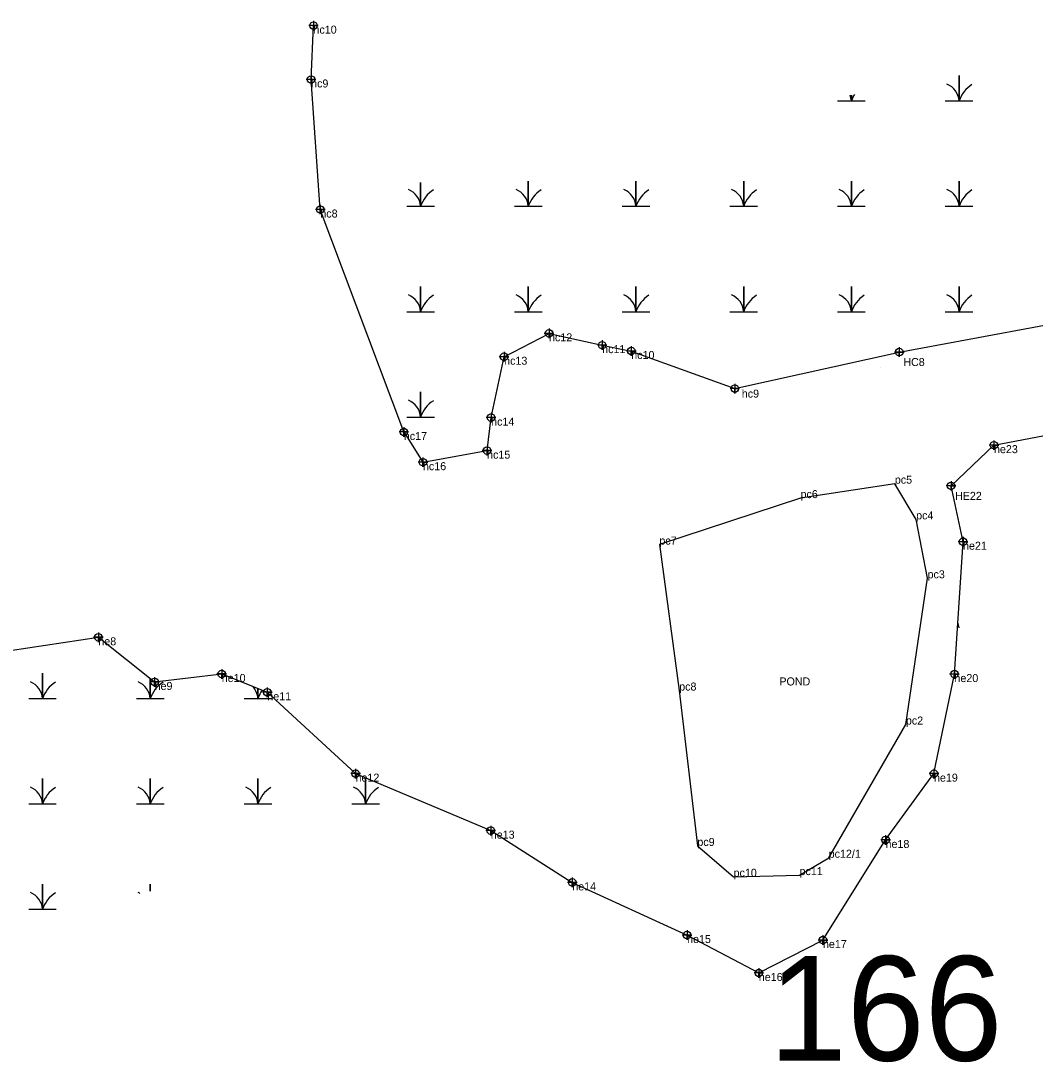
# Model space of a CAD drawing. Extents: x 2072529 to 2268796, y 436423 to 470406.
# Drawn here: x 2184796 to 2185430, y 452796 to 453446 of the extents above; entities that cross this region are included whole.
import ezdxf

# ---------------------------------------------------------------- set-up
doc = ezdxf.new("R2010")
doc.units = 0
for name, color, linetype in [('Default', 7, 'Continuous'), ('Exist Environmental Wetland Boundary', 7, 'Continuous'), ('Exist Environmental Wetland Boundary Cogo Comment', 7, 'Continuous'), ('Exist Environmental Wetland Boundary Cogo Point CELL', 7, 'Continuous'), ('Exist Hydro Jurisdictional Stream or Body of Water NEU Mitigable Cogo Comment', 7, 'Continuous'), ('Old_Level_20', 7, 'Continuous'), ('Old_Level_52', 7, 'Continuous')]:
    doc.layers.add(name, color=color, linetype=linetype)

msp = doc.modelspace()

# ---------------------------------------------------------------- linework, layer by layer
at = {"layer": 'Exist Environmental Wetland Boundary'}
for points in [[(2184979.12, 453446.03), (2184979.12, 453440.03), (2184979.12, 453443.03), (2184982.12, 453443.03), (2184976.12, 453443.03)], [(2184977.65, 453412.42), (2184977.65, 453406.42), (2184977.65, 453409.42), (2184980.65, 453409.42), (2184974.65, 453409.42)], [(2184983.4, 453331.2), (2184983.4, 453325.2), (2184983.4, 453328.2), (2184986.4, 453328.2), (2184980.4, 453328.2)], [(2185126.21, 453253.87), (2185126.21, 453247.87), (2185126.21, 453250.87), (2185129.21, 453250.87), (2185123.21, 453250.87)], [(2185159.4, 453246.51), (2185159.4, 453240.51), (2185159.4, 453243.51), (2185162.4, 453243.51), (2185156.4, 453243.51)], [(2185098.16, 453239.27), (2185098.16, 453233.27), (2185098.16, 453236.27), (2185101.16, 453236.27), (2185095.16, 453236.27)], [(2185177.54, 453242.84), (2185177.54, 453236.84), (2185177.54, 453239.84), (2185180.54, 453239.84), (2185174.54, 453239.84)], [(2185344.94, 453242.21), (2185344.94, 453236.21), (2185344.94, 453239.21), (2185347.94, 453239.21), (2185341.94, 453239.21)], [(2185242.22, 453219.35), (2185242.22, 453213.35), (2185242.22, 453216.35), (2185245.22, 453216.35), (2185239.22, 453216.35)], [(2185090.05, 453201.25), (2185090.05, 453195.25), (2185090.05, 453198.25), (2185093.05, 453198.25), (2185087.05, 453198.25)], [(2185035.54, 453192.27), (2185035.54, 453186.27), (2185035.54, 453189.27), (2185038.54, 453189.27), (2185032.54, 453189.27)], [(2185087.53, 453180.63), (2185087.53, 453174.63), (2185087.53, 453177.63), (2185090.53, 453177.63), (2185084.53, 453177.63)], [(2185404.06, 453184.06), (2185404.06, 453178.06), (2185404.06, 453181.06), (2185407.06, 453181.06), (2185401.06, 453181.06)], [(2185047.47, 453173.42), (2185047.47, 453167.42), (2185047.47, 453170.42), (2185050.47, 453170.42), (2185044.47, 453170.42)], [(2185377.23, 453158.63), (2185377.23, 453152.63), (2185377.23, 453155.63), (2185380.23, 453155.63), (2185374.23, 453155.63)], [(2185384.73, 453123.74), (2185384.73, 453117.74), (2185384.73, 453120.74), (2185387.73, 453120.74), (2185381.73, 453120.74)], [(2184844.78, 453064.05), (2184844.78, 453058.05), (2184844.78, 453061.05), (2184847.78, 453061.05), (2184841.78, 453061.05)], [(2184879.9, 453036.18), (2184879.9, 453030.18), (2184879.9, 453033.18), (2184882.9, 453033.18), (2184876.9, 453033.18)], [(2184921.85, 453041.15), (2184921.85, 453035.15), (2184921.85, 453038.15), (2184924.85, 453038.15), (2184918.85, 453038.15)], [(2185379.38, 453041.1), (2185379.38, 453035.1), (2185379.38, 453038.1), (2185382.38, 453038.1), (2185376.38, 453038.1)], [(2184950.29, 453029.71), (2184950.29, 453023.71), (2184950.29, 453026.71), (2184953.29, 453026.71), (2184947.29, 453026.71)], [(2185005.39, 452978.93), (2185005.39, 452972.93), (2185005.39, 452975.93), (2185008.39, 452975.93), (2185002.39, 452975.93)], [(2185366.6, 452978.91), (2185366.6, 452972.91), (2185366.6, 452975.91), (2185369.6, 452975.91), (2185363.6, 452975.91)], [(2185089.84, 452943.32), (2185089.84, 452937.32), (2185089.84, 452940.32), (2185092.84, 452940.32), (2185086.84, 452940.32)], [(2185336.35, 452937.49), (2185336.35, 452931.49), (2185336.35, 452934.49), (2185339.35, 452934.49), (2185333.35, 452934.49)], [(2185140.72, 452911), (2185140.72, 452905), (2185140.72, 452908), (2185143.72, 452908), (2185137.72, 452908)], [(2185212.43, 452878.12), (2185212.43, 452872.12), (2185212.43, 452875.12), (2185215.43, 452875.12), (2185209.43, 452875.12)], [(2185297.24, 452875.01), (2185297.24, 452869.01), (2185297.24, 452872.01), (2185300.24, 452872.01), (2185294.24, 452872.01)], [(2185257.21, 452854.43), (2185257.21, 452848.43), (2185257.21, 452851.43), (2185260.21, 452851.43), (2185254.21, 452851.43)]]:
    msp.add_lwpolyline(points, dxfattribs=at)
for centre in [(2184979.12, 453443.03), (2184977.65, 453409.42), (2184983.4, 453328.2), (2185126.21, 453250.87), (2185159.4, 453243.51), (2185098.16, 453236.27), (2185177.54, 453239.84), (2185344.94, 453239.21), (2185242.22, 453216.35), (2185090.05, 453198.25), (2185035.54, 453189.27), (2185087.53, 453177.63), (2185404.06, 453181.06), (2185047.47, 453170.42), (2185377.23, 453155.63), (2185384.73, 453120.74), (2184844.78, 453061.05), (2184921.85, 453038.15), (2185379.38, 453038.1), (2184879.9, 453033.18), (2184950.29, 453026.71), (2185005.39, 452975.93), (2185366.6, 452975.91), (2185089.84, 452940.32), (2185336.35, 452934.49), (2185140.72, 452908), (2185212.43, 452875.12), (2185297.24, 452872.01), (2185257.21, 452851.43)]:
    msp.add_circle(centre, 2.34, dxfattribs=at)
at = {"layer": 'Exist Environmental Wetland Boundary Cogo Point CELL'}
for points in [[(2185373.67, 453396.01), (2185382.27, 453396.01), (2185382.27, 453411.79), (2185382.27, 453396.01), (2185390.87, 453396.01)], [(2185306.42, 453396.01), (2185315.02, 453396.01), (2185315.02, 453399.69)], [(2185315.02, 453399.69), (2185315.02, 453396.01), (2185323.62, 453396.01)], [(2185037.42, 453330.21), (2185046.02, 453330.21), (2185046.02, 453345)], [(2185046.02, 453345), (2185046.02, 453330.21), (2185054.62, 453330.21)], [(2185104.67, 453330.21), (2185113.27, 453330.21), (2185113.27, 453345.99), (2185113.27, 453330.21), (2185121.87, 453330.21)], [(2185171.92, 453330.21), (2185180.52, 453330.21), (2185180.52, 453345.99), (2185180.52, 453330.21), (2185189.12, 453330.21)], [(2185239.17, 453330.21), (2185247.77, 453330.21), (2185247.77, 453345.99), (2185247.77, 453330.21), (2185256.37, 453330.21)], [(2185306.42, 453330.21), (2185315.02, 453330.21), (2185315.02, 453345.99), (2185315.02, 453330.21), (2185323.62, 453330.21)], [(2185373.67, 453330.21), (2185382.27, 453330.21), (2185382.27, 453345.99), (2185382.27, 453330.21), (2185390.87, 453330.21)], [(2185037.42, 453264.41), (2185046.02, 453264.41), (2185046.02, 453280.19), (2185046.02, 453264.41), (2185054.62, 453264.41)], [(2185104.67, 453264.41), (2185113.27, 453264.41), (2185113.27, 453280.19), (2185113.27, 453264.41), (2185121.87, 453264.41)], [(2185171.92, 453264.41), (2185180.52, 453264.41), (2185180.52, 453280.19), (2185180.52, 453264.41), (2185189.12, 453264.41)], [(2185239.17, 453264.41), (2185247.77, 453264.41), (2185247.77, 453280.19), (2185247.77, 453264.41), (2185256.37, 453264.41)], [(2185306.42, 453264.41), (2185315.02, 453264.41), (2185315.02, 453280.19), (2185315.02, 453264.41), (2185323.62, 453264.41)], [(2185373.67, 453264.41), (2185382.27, 453264.41), (2185382.27, 453280.19), (2185382.27, 453264.41), (2185390.87, 453264.41)], [(2185037.42, 453198.61), (2185046.02, 453198.61), (2185046.02, 453214.39), (2185046.02, 453198.61), (2185054.62, 453198.61)], [(2184801.35, 453022.81), (2184809.95, 453022.81), (2184809.95, 453038.59), (2184809.95, 453022.81), (2184818.55, 453022.81)], [(2184868.6, 453022.81), (2184877.2, 453022.81), (2184877.2, 453035.32)], [(2184877.2, 453035.32), (2184877.2, 453022.81), (2184885.8, 453022.81)], [(2184935.85, 453022.81), (2184944.45, 453022.81), (2184944.45, 453029.06)], [(2184944.45, 453029.06), (2184944.45, 453022.81), (2184953.05, 453022.81)], [(2184801.35, 452957.01), (2184809.95, 452957.01), (2184809.95, 452972.79), (2184809.95, 452957.01), (2184818.55, 452957.01)], [(2184868.6, 452957.01), (2184877.2, 452957.01), (2184877.2, 452972.79), (2184877.2, 452957.01), (2184885.8, 452957.01)], [(2184935.85, 452957.01), (2184944.45, 452957.01), (2184944.45, 452972.79), (2184944.45, 452957.01), (2184953.05, 452957.01)], [(2185003.1, 452957.01), (2185011.7, 452957.01), (2185011.7, 452972.79), (2185011.7, 452957.01), (2185020.3, 452957.01)], [(2184801.35, 452891.21), (2184809.95, 452891.21), (2184809.95, 452906.99), (2184809.95, 452891.21), (2184818.55, 452891.21)], [(2184877.2, 452902.49), (2184877.2, 452906.99), (2184877.2, 452902.49)]]:
    msp.add_lwpolyline(points, dxfattribs=at)
for centre, radius, start, end in [((2185370, 453395.12), 12.3, 4.14034, 67.53497), ((2185400.51, 453389.95), 19.22, 122.12745, 161.62219), ((2185333.26, 453389.95), 19.22, 148.17741, 161.62219), ((2185302.75, 453395.12), 12.3, 4.14034, 21.0382), ((2185033.75, 453329.32), 12.3, 4.14034, 67.53497), ((2185064.26, 453324.15), 19.22, 122.12745, 161.62219), ((2185101, 453329.32), 12.3, 4.14034, 67.53497), ((2185131.51, 453324.15), 19.22, 122.12745, 161.62219), ((2185168.25, 453329.32), 12.3, 4.14034, 67.53497), ((2185198.76, 453324.15), 19.22, 122.12745, 161.62219), ((2185235.5, 453329.32), 12.3, 4.14034, 67.53497), ((2185266.01, 453324.15), 19.22, 122.12745, 161.62219), ((2185302.75, 453329.32), 12.3, 4.14034, 67.53497), ((2185333.26, 453324.15), 19.22, 122.12745, 161.62219), ((2185370, 453329.32), 12.3, 4.14034, 67.53497), ((2185400.51, 453324.15), 19.22, 122.12745, 161.62219), ((2185033.75, 453263.52), 12.3, 4.14034, 67.53497), ((2185064.26, 453258.35), 19.22, 122.12745, 161.62219), ((2185101, 453263.52), 12.3, 4.14034, 67.53497), ((2185131.51, 453258.35), 19.22, 122.12745, 161.62219), ((2185168.25, 453263.52), 12.3, 4.14034, 67.53497), ((2185198.76, 453258.35), 19.22, 122.12745, 161.62219), ((2185235.5, 453263.52), 12.3, 4.14034, 67.53497), ((2185266.01, 453258.35), 19.22, 122.12745, 161.62219), ((2185302.75, 453263.52), 12.3, 4.14034, 67.53497), ((2185333.26, 453258.35), 19.22, 122.12745, 161.62219), ((2185370, 453263.52), 12.3, 4.14034, 67.53497), ((2185400.51, 453258.35), 19.22, 122.12745, 161.62219), ((2185033.75, 453197.72), 12.3, 4.14034, 67.53497), ((2185064.26, 453192.55), 19.22, 122.12745, 161.62219), ((2185370, 453066.12), 12.3, 4.14034, 21.05335), ((2184797.68, 453021.92), 12.3, 4.14034, 67.53497), ((2184828.19, 453016.75), 19.22, 122.12745, 161.62219), ((2184864.93, 453021.92), 12.3, 4.14034, 67.53497), ((2184895.44, 453016.75), 19.22, 122.12745, 161.62219), ((2184932.18, 453021.92), 12.3, 4.14034, 43.67086), ((2184962.69, 453016.75), 19.22, 144.20108, 161.62219), ((2184797.68, 452956.12), 12.3, 4.14034, 67.53497), ((2184828.19, 452950.95), 19.22, 122.12745, 161.62219), ((2184864.93, 452956.12), 12.3, 4.14034, 67.53497), ((2184895.44, 452950.95), 19.22, 122.12745, 161.62219), ((2184932.18, 452956.12), 12.3, 4.14034, 67.53497), ((2184962.69, 452950.95), 19.22, 122.12745, 161.62219), ((2184999.43, 452956.12), 12.3, 4.14034, 67.53497), ((2185029.94, 452950.95), 19.22, 122.12745, 161.62219), ((2184797.68, 452890.32), 12.3, 4.14034, 67.53497), ((2184828.19, 452885.15), 19.22, 122.12745, 161.62219), ((2184864.93, 452890.32), 12.3, 61.92098, 67.53497)]:
    msp.add_arc(centre, radius, start, end, dxfattribs=at)
at = {"layer": 'Old_Level_20'}
for p, q in [((2184979.12, 453443.03), (2184979.12, 453443.03)), ((2184977.65, 453409.42), (2184977.65, 453409.42)), ((2184983.4, 453328.2), (2184983.4, 453328.2)), ((2185126.21, 453250.87), (2185126.21, 453250.87)), ((2185159.4, 453243.51), (2185159.4, 453243.51)), ((2185177.54, 453239.84), (2185177.54, 453239.84)), ((2185098.16, 453236.27), (2185098.16, 453236.27)), ((2185332.93, 453229.41), (2185332.93, 453229.41)), ((2185246.58, 453215.74), (2185246.58, 453215.74)), ((2185090.05, 453198.25), (2185090.05, 453198.25)), ((2185035.54, 453189.27), (2185035.54, 453189.27)), ((2185404.06, 453181.06), (2185404.06, 453181.06)), ((2185087.53, 453177.63), (2185087.53, 453177.63)), ((2185047.47, 453170.42), (2185047.47, 453170.42)), ((2185379.42, 453161.76), (2185379.42, 453161.76)), ((2185342.14, 453156.99), (2185342.14, 453156.99)), ((2185283.27, 453147.97), (2185283.27, 453147.97)), ((2185355.44, 453134.7), (2185355.44, 453134.7)), ((2185384.73, 453120.74), (2185384.73, 453120.74)), ((2185195.12, 453118.93), (2185195.12, 453118.93)), ((2185362.58, 453097.89), (2185362.58, 453097.89)), ((2184844.78, 453061.05), (2184844.78, 453061.05)), ((2184921.85, 453038.15), (2184921.85, 453038.15)), ((2185379.38, 453038.1), (2185379.38, 453038.1)), ((2184879.9, 453033.18), (2184879.9, 453033.18)), ((2184950.29, 453026.71), (2184950.29, 453026.71)), ((2185207.48, 453027.8), (2185207.48, 453027.8)), ((2185349.06, 453006.57), (2185349.06, 453006.57)), ((2185005.39, 452975.93), (2185005.39, 452975.93)), ((2185366.6, 452975.91), (2185366.6, 452975.91)), ((2185089.84, 452940.32), (2185089.84, 452940.32)), ((2185336.35, 452934.49), (2185336.35, 452934.49)), ((2185218.84, 452930.77), (2185218.84, 452930.77)), ((2185300.84, 452923.4), (2185300.84, 452923.4)), ((2185282.63, 452912.55), (2185282.63, 452912.55)), ((2185140.72, 452908), (2185140.72, 452908)), ((2185241.45, 452911.51), (2185241.45, 452911.51)), ((2185212.43, 452875.12), (2185212.43, 452875.12)), ((2185297.24, 452872.01), (2185297.24, 452872.01)), ((2185257.21, 452851.43), (2185257.21, 452851.43))]:
    msp.add_line(p, q, dxfattribs=at)
for points in [[(2185035.54, 453189.27), (2184983.4, 453328.2), (2184977.65, 453409.42), (2184979.12, 453443.03)], [(2185035.54, 453189.27), (2184983.4, 453328.2), (2184977.65, 453409.42), (2184979.12, 453443.03)], [(2185035.54, 453189.27), (2185047.47, 453170.42), (2185087.53, 453177.63), (2185090.05, 453198.25), (2185098.16, 453236.27), (2185126.21, 453250.87), (2185159.4, 453243.51), (2185177.54, 453239.84), (2185242.22, 453216.35), (2185344.94, 453239.21), (2185481.7, 453264.48), (2185602.96, 453294.86), (2185721.74, 453322.09), (2185796.34, 453338.15), (2185846.75, 453343.9), (2185952.49, 453364.25), (2185987.26, 453373.96), (2186006.22, 453363.32), (2186024.19, 453324.8)], [(2185035.54, 453189.27), (2185047.47, 453170.42), (2185087.53, 453177.63), (2185090.05, 453198.25), (2185098.16, 453236.27), (2185126.21, 453250.87), (2185159.4, 453243.51), (2185177.54, 453239.84)], [(2184734.36, 453044.59), (2184844.78, 453061.05), (2184879.9, 453033.18), (2184921.85, 453038.15), (2184950.29, 453026.71), (2185005.39, 452975.93), (2185089.84, 452940.32), (2185140.72, 452908), (2185212.43, 452875.12), (2185257.21, 452851.43), (2185297.24, 452872.01), (2185336.35, 452934.49), (2185366.6, 452975.91), (2185379.38, 453038.1), (2185384.73, 453120.74), (2185377.23, 453155.63), (2185404.06, 453181.06), (2185488.04, 453196.98)], [(2184430.06, 452870.49), (2184414.61, 452891.04), (2184410.74, 452919.14), (2184389.78, 452979.2), (2184468.45, 452994.37), (2184572.88, 453014.51), (2184734.36, 453044.59), (2184844.78, 453061.05), (2184879.9, 453033.18), (2184921.85, 453038.15), (2184950.29, 453026.71), (2185005.39, 452975.93), (2185089.84, 452940.32), (2185140.72, 452908), (2185212.43, 452875.12), (2185257.21, 452851.43), (2185297.24, 452872.01), (2185336.35, 452934.49), (2185366.6, 452975.91), (2185379.38, 453038.1), (2185384.73, 453120.74)]]:
    msp.add_lwpolyline(points, dxfattribs=at)
at = {"layer": 'Old_Level_52'}
msp.add_lwpolyline([(2185300.84, 452923.4), (2185349.06, 453006.57), (2185362.58, 453097.89), (2185355.44, 453134.7), (2185342.14, 453156.99), (2185283.27, 453147.97), (2185195.12, 453118.93), (2185207.48, 453027.8), (2185218.84, 452930.77), (2185241.45, 452911.51), (2185282.63, 452912.55)], close=True, dxfattribs=at)

# ---------------------------------------------------------------- texts
at = {"layer": 'Default'}
msp.add_text('166', height=65.34, dxfattribs=at).set_placement((2185263.56, 452796.66))
at = {"layer": 'Exist Environmental Wetland Boundary Cogo Comment'}
for s, p in [('hc10', (2184979.12, 453438.03)), ('hc9', (2184977.65, 453404.42)), ('hc8', (2184983.4, 453323.2)), ('hc12', (2185126.21, 453245.87)), ('hc11', (2185159.4, 453238.51)), ('hc10', (2185177.54, 453234.84)), ('hc13', (2185098.16, 453231.27)), ('HC8', (2185347.44, 453230.46)), ('hc9', (2185246.58, 453210.74)), ('hc14', (2185090.05, 453193.25)), ('hc17', (2185035.54, 453184.27)), ('he23', (2185404.06, 453176.06)), ('hc15', (2185087.53, 453172.63)), ('hc16', (2185047.47, 453165.42)), ('HE22', (2185379.73, 453146.88)), ('he21', (2185384.73, 453115.74)), ('he8', (2184844.78, 453056.05)), ('he10', (2184921.85, 453033.15)), ('he20', (2185379.38, 453033.1)), ('he9', (2184879.9, 453028.18)), ('he11', (2184950.29, 453021.71)), ('he12', (2185005.39, 452970.93)), ('he19', (2185366.6, 452970.91)), ('he13', (2185089.84, 452935.32)), ('he18', (2185336.35, 452929.49)), ('he14', (2185140.72, 452903)), ('he15', (2185212.43, 452870.12)), ('he17', (2185297.24, 452867.01)), ('he16', (2185257.21, 452846.43))]:
    msp.add_text(s, height=5, dxfattribs=at).set_placement(p)
at = {"layer": 'Exist Hydro Jurisdictional Stream or Body of Water NEU Mitigable Cogo Comment'}
for s, p in [('pc5', (2185342.14, 453156.99)), ('pc6', (2185283.27, 453147.97)), ('pc4', (2185355.44, 453134.7)), ('pc7', (2185195.12, 453118.93)), ('pc3', (2185362.58, 453097.89)), ('POND', (2185270.05, 453030.99)), ('pc8', (2185207.48, 453027.8)), ('pc2', (2185349.06, 453006.57)), ('pc9', (2185218.84, 452930.77)), ('pc12/1', (2185300.84, 452923.4)), ('pc10', (2185241.45, 452911.51)), ('pc11', (2185282.63, 452912.55))]:
    msp.add_text(s, height=5, dxfattribs=at).set_placement(p)

doc.saveas('drawing.dxf')
